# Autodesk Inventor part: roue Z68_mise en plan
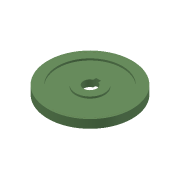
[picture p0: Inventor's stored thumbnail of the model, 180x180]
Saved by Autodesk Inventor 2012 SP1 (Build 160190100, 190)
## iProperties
Created: 2011-10
Part Number: roue Z68_mise en plan
Document SubType Name: Modeling
Designer: Bruno
Material: Par défaut
Mass: 20.3087 g
Surface Area: 99.2904 cm^2
Volume: 20.3087 cm^3
Density: 1 g/cm^3
Author: Bruno
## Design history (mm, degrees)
feature "Base1"
sketch "Esquisse2"
  geometry: C1 r 27 at (0, 0) reference; C2 r 5.5 at (34.859, -17.488) reference; C3 r 33.5 at (0, 0)
  constraints: 1 centre point, 1 coincident, 1 tangent
feature "SrfExtrusion1" sketch "Esquisse2" dims "d0" = 8, "d1" = 0
node "Solide1"
node "Corps solides"
node "Corps surfaciques"
node "Référence2"
body "Srf1"
